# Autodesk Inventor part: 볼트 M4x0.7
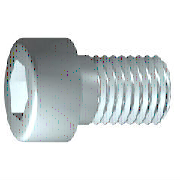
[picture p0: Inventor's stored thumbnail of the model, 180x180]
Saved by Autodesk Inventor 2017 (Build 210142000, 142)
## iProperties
IsCustomPart: 0
Created: 2012-02
Part Number: 볼트 M4x0.7
Material: 스테인리스강
Description: 6각 소켓 머리 캡 나사
Document SubType Name: Modeling
Standard: ISO 4762
Designer: mduedu
Standard Revision: Fourth edition 2004-03-01
Standards Organization: ISO
Language: ko-KR
Size Designation: M4 x 12
Categories: <MemberInstance><Categories><Category DisplayName="조임쇠" InternalName="e4da775c-781d-43d5-af7c-5136215cf5a6" Mnemonic="FSTN"><Category DisplayName="볼트" InternalN
Density: 7.75 g/cm^3
Appearance: 반광택
Author: mduedu
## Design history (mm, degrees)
sketch "스케치1"
  geometry: L1 (-1, 0)-(12, 0); L2 (12, 0)-(12, 2); L3 (12, 2)-(1.75, 2); L4 (1.75, 2)-(1.32, 2); L5 (1.32, 2)-(0, 2); L6 (0, 2)-(0, 3.5); L7 (0, 3.5)-(-4, 3.5); L8 (-4, 3.5)-(-4, 1.732); L9 (-4, 1.732)-(-2, 1.732); L10 (-2, 1.732)-(-1, 0); L11 (-7.2, 0)-(15.2, 0) reference; L12 (0, -0.7)-(0, 4.2) reference; L13 (1.75, 2)-(0, 2)
  constraints: 22 end point, 6 parallel, 2 collinear, 2 perpendicular, 1 horizontal, 1 point on line
  dimensions: "d1" = 10.25 distance from line of L3.end L2 (= GEL); "d2" = 0.42952 distance of L4.end L3.end (computed from GAL); "d3" = 4 distance between parallel lines of L8 L6 (= KOH); "d4" = 2 distance of L8.end L9.end (= INTI); "d5" = 60 deg angle of L10 L1; "d6" = 4 diameter of L3 L1 (= GD); "d7" = 4 diameter of L5 L1 (= BDM); "d8" = 3.4641 diameter of L9 L1 (= 1.1547 x SW); "d9" = 7 diameter of L7 L1 (= KOD); "d26" = 12 distance between parallel lines of L12 L2 (= NLG)
revolve "본체" sketch "스케치1" stored, may be unused: angle "d10" = 90 deg
sketch "스케치2"
  geometry: L1 (0, -4.9)-(0, 4.9) reference; L2 (-4.9, 0)-(4.9, 0) reference; L3 (1.732, 0)-(0.866, -1.5); L4 (0.866, -1.5)-(-0.866, -1.5); L5 (-0.866, -1.5)-(-1.732, 0); L6 (-1.732, 0)-(-0.866, 1.5); L7 (-0.866, 1.5)-(0.866, 1.5); L8 (0.866, 1.5)-(1.732, 0); 2 further points
  constraints: 12 end point, 1 coincident, 1 horizontal alignment, 1 point on line, 12 other
extrude "슬롯" join sketch "스케치2" stored distance "d11" = 10; taper "d12" = 0 deg
workplane "Work Plane1"
fillet "Fillet2" dims "d30" = 0.1 (= R)
body "Solid1"
fillet "모깎기1" dims "d17" = 0.4 (= RR)
feature "스레드" dims "d13" = 10.25 (= GEL), "d14" = 0
chamfer "모따기1" distance "d15" = 0.42941 (= -0.5 x SPD + 0.5 x GD); stored, may be unused: second distance "d16" = 0.42941 (= GUL), angle "d27" = 45 deg
other parameters: "GD" = 4 [user parameter; used in 2 equation terms], "NLG" = 12 [user parameter; used in 1 equation term], "GEL" = 10.25 [user parameter; used in 2 equation terms], "KOD" = 7 [user parameter; used in 1 equation term], "KOH" = 4 [user parameter; used in 1 equation term], "INTI" = 2 [user parameter; used in 1 equation term], "GAL" = 0.42941 (= 0.61345 x PTC) [user parameter; used in 1 equation term], "GUL" = 0.42941 (= 0.61345 x PTC) [user parameter; used in 1 equation term], "BDM" = 4 (= NND) [user parameter; used in 1 equation term], "SW" = 3 [user parameter; used in 2 equation terms], "RR" = 0.4 [user parameter; used in 1 equation term], "SPD" = 3.14117 (= NND - 1.2269 x PTC) [user parameter; used in 1 equation term], "d19" = 0, "d28" = 0, "d29" = 0, "R" = 0.1 [user parameter; used in 1 equation term], "TOA" = 30 deg [user parameter], "GD1" = 3.14117 (= THREADDIA - 1.2269 x PTC) [user parameter], "THREADDIA" = 4 [user parameter; used in 1 equation term], "FAWI" = 45 deg [user parameter], "TPU" = 14.28571 (computed from PTC) [user parameter], "PTC" = 0.7 [user parameter; used in 5 equation terms], "NND" = 4 [user parameter; used in 2 equation terms], "E0" = 3.465 (= 1.155 x SW) [user parameter]
